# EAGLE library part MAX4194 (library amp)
MAX4194 Instrumentation AMP. Producted by MAXIM.Co
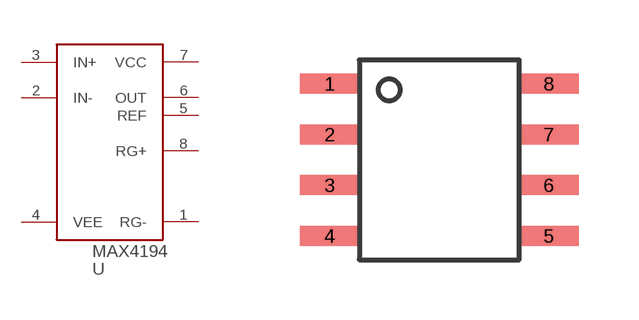
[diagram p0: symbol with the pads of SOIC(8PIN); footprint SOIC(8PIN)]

Designator prefix U

## MAX4194  [SOIC(8PIN)]
1  RG-
2  IN-
3  IN+
4  VEE
5  REF
6  OUT
7  VCC
8  RG+

## Footprint SOIC(8PIN) (pad centres in mm)
4*5mm size , 0.05inch pitch , 8pin pacage
smd 1.5 x 0.5: 1 -2.74,1.905; 2 -2.74,0.635; 3 -2.74,-0.635; 4 -2.74,-1.905; 5 2.74,-1.905; 6 2.74,-0.635; 7 2.74,0.635; 8 2.74,1.905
